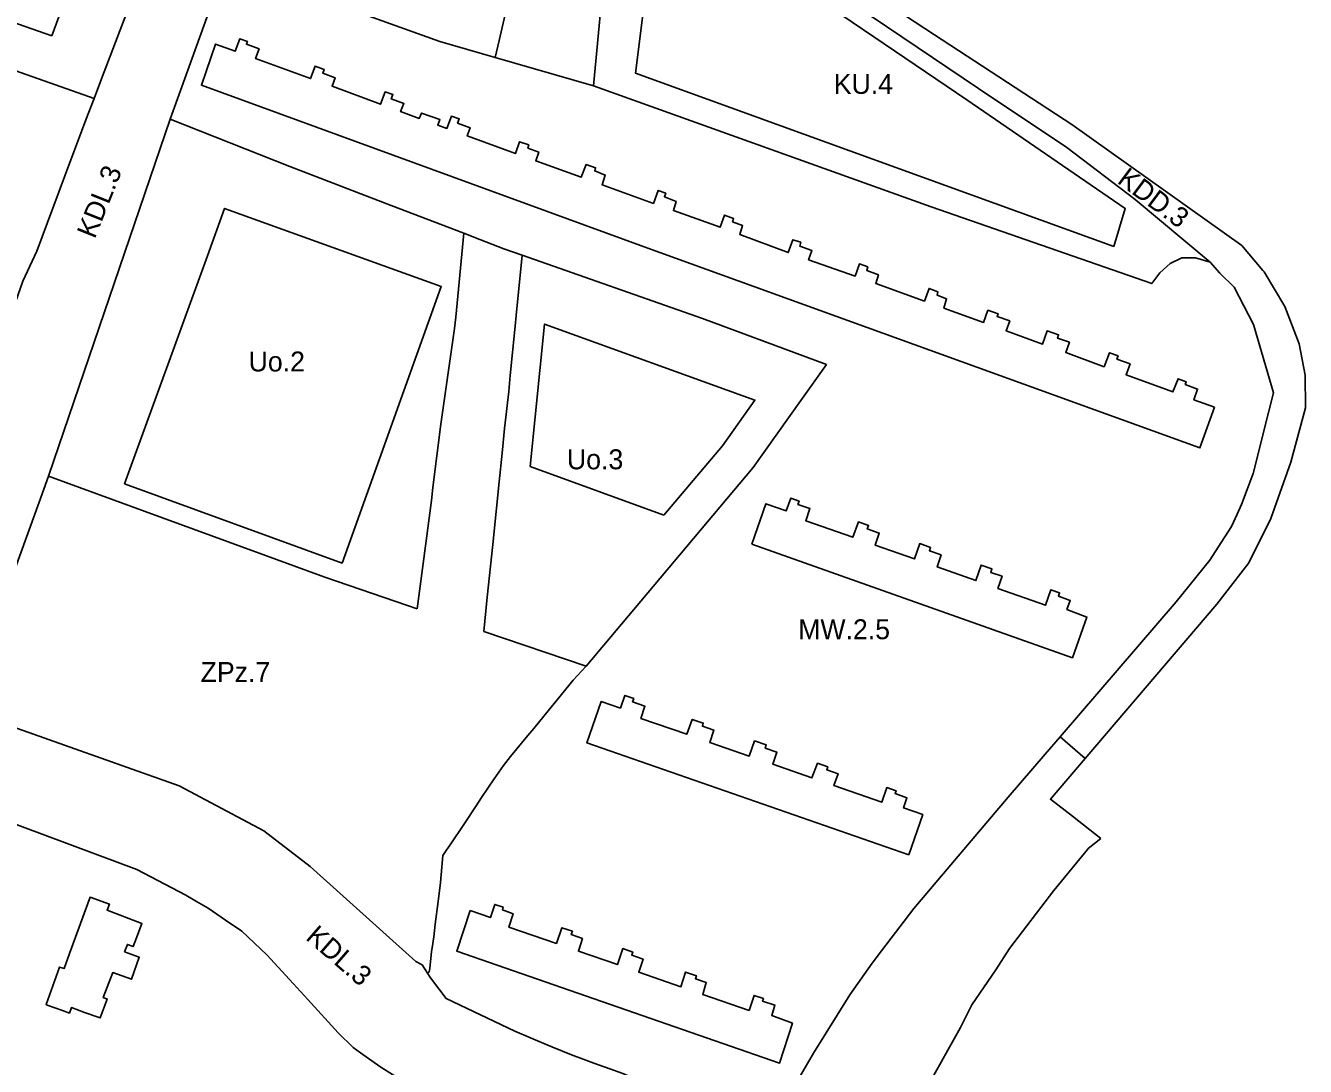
# Model space of a CAD drawing. Extents: x 7428239 to 7429836, y 5549133 to 5550853.
# Drawn here: x 7429316.4 to 7429637.4, y 5550005.5 to 5550266.4 of the extents above; entities that cross this region are included whole.
import ezdxf

# ---------------------------------------------------------------- set-up
doc = ezdxf.new("R2010")
doc.units = 0
for name, color, linetype in [('LIN_linie rozgraniczające', 7, 'Continuous'), ('LIN_nieprzekraczalna linia zabudowy', 7, 'Continuous'), ('LIN_obowiązująca linia zabudowy', 7, 'Continuous'), ('TXT_Oznaczenia Przeznaczenia', 7, 'Continuous')]:
    doc.layers.add(name, color=color, linetype=linetype)

msp = doc.modelspace()

# ---------------------------------------------------------------- linework, layer by layer
at = {"layer": 'LIN_linie rozgraniczające'}
for p, q in [((7429436.32, 5550210.49), (7429440.9, 5550208.88)), ((7429626.71, 5550205.06), (7429621.44, 5550211.32)), ((7429440.9, 5550208.88), (7429486.15, 5550192.99)), ((7429439.22, 5550191.08), (7429437.95, 5550178.73)), ((7429486.15, 5550192.99), (7429517.29, 5550181.44)), ((7429420.58, 5550166.49), (7429424, 5550190.47)), ((7429517.29, 5550181.44), (7429510.86, 5550172.43)), ((7429437.95, 5550178.73), (7429437.57, 5550174.72)), ((7429437.57, 5550174.72), (7429436.55, 5550165.42)), ((7429510.86, 5550172.43), (7429498.86, 5550155.59)), ((7429418.58, 5550150.58), (7429420.58, 5550166.49)), ((7429436.55, 5550165.42), (7429435.95, 5550159.23)), ((7429435.95, 5550159.23), (7429435.2, 5550152.04)), ((7429498.86, 5550155.59), (7429468.91, 5550120.01)), ((7429322.17, 5550153.49), (7429319.78, 5550146.91)), ((7429391.47, 5550128.12), (7429322.17, 5550153.49)), ((7429435.2, 5550152.04), (7429434.43, 5550144.6)), ((7429418.19, 5550147.38), (7429418.58, 5550150.58)), ((7429622.76, 5550150.12), (7429621.32, 5550146.35)), ((7429319.78, 5550146.91), (7429300.94, 5550094.93)), ((7429414.59, 5550120.17), (7429418.19, 5550147.38)), ((7429621.32, 5550146.35), (7429620.24, 5550143.9)), ((7429434.43, 5550144.6), (7429433.58, 5550136.29)), ((7429620.24, 5550143.9), (7429618.82, 5550140.85)), ((7429618.82, 5550140.85), (7429615.52, 5550135.69)), ((7429433.58, 5550136.29), (7429432.18, 5550123.15)), ((7429615.52, 5550135.69), (7429613.41, 5550132.37)), ((7429613.41, 5550132.37), (7429604.96, 5550121.96)), ((7429412.17, 5550121), (7429391.47, 5550128.12)), ((7429432.18, 5550123.15), (7429431.33, 5550114.49)), ((7429414.59, 5550120.17), (7429412.17, 5550121)), ((7429468.91, 5550120.01), (7429456.98, 5550105.85)), ((7429456.98, 5550105.85), (7429431.33, 5550114.49)), ((7429300.94, 5550094.93), (7429354.94, 5550075.82)), ((7429562.83, 5550073.01), (7429572.11, 5550083.77)), ((7429354.94, 5550075.82), (7429376.19, 5550064.53)), ((7429539.14, 5550045.03), (7429562.83, 5550073.01)), ((7429376.19, 5550064.53), (7429387.81, 5550055.56)), ((7429574.24, 5550049.55), (7429582.68, 5550059.88)), ((7429356.56, 5550048.42), (7429344.3, 5550054.83)), ((7429387.81, 5550055.56), (7429414.27, 5550031.8)), ((7429563.14, 5550035.03), (7429574.24, 5550049.55)), ((7429359.3, 5550046.83), (7429356.56, 5550048.42)), ((7429362.17, 5550045.15), (7429359.3, 5550046.83)), ((7429366.58, 5550042.12), (7429362.17, 5550045.15)), ((7429531.03, 5550034.42), (7429539.14, 5550045.03)), ((7429370.62, 5550039.34), (7429366.58, 5550042.12)), ((7429528.7, 5550031.36), (7429531.03, 5550034.42)), ((7429559.75, 5550029.69), (7429563.14, 5550035.03)), ((7429414.27, 5550031.8), (7429415.83, 5550030.94)), ((7429541.25, 5549998.1), (7429550.86, 5550015.24))]:
    msp.add_line(p, q, dxfattribs=at)
for points in [[(7429333.65, 5550248.11), (7429335.43, 5550253.06), (7429343.97, 5550275.43), (7429346.12, 5550281.11), (7429349.62, 5550291.37), (7429352.13, 5550298.07), (7429354.31, 5550304.49), (7429358.66, 5550316.28), (7429359.7, 5550319.12), (7429359.85, 5550319.51), (7429360.39, 5550320.84), (7429364.51, 5550332.56), (7429367.83, 5550342), (7429373.86, 5550361.39), (7429373.64, 5550361.47), (7429373.69, 5550361.59), (7429379.7, 5550383.03), (7429382.96, 5550395.63), (7429386.85, 5550410.17), (7429388.64, 5550416.92), (7429387.69, 5550418.78), (7429393.23, 5550417.3), (7429395.22, 5550416.69), (7429395.87, 5550416.55)], [(7429389.87, 5550345.68), (7429388.42, 5550341.87), (7429385.98, 5550335.46), (7429366.61, 5550281.72), (7429352.66, 5550243), (7429322.17, 5550153.49)], [(7429450.22, 5550317.09), (7429458.17, 5550313.11), (7429461.8, 5550311.2), (7429462.58, 5550309.18), (7429463.3, 5550306.22), (7429463.68, 5550302.76), (7429458.81, 5550251.34), (7429434.17, 5550258.44), (7429420.31, 5550262.43), (7429366.61, 5550281.72)], [(7429450.22, 5550317.09), (7429447.11, 5550312.82), (7429446.17, 5550308.93), (7429444.68, 5550302.56), (7429442.66, 5550294.78), (7429442.04, 5550291.98), (7429440.91, 5550287.07), (7429439.37, 5550280.38), (7429437.82, 5550273.93), (7429437.46, 5550272.49), (7429435.18, 5550262.68), (7429434.17, 5550258.44)], [(7429621.44, 5550211.32), (7429578.76, 5550241.61), (7429544.37, 5550264.14), (7429461.51, 5550318.42)], [(7429478.7, 5550302.35), (7429555.39, 5550250.67)], [(7429333.65, 5550248.11), (7429309.59, 5550256.62), (7429296, 5550261.33), (7429292.19, 5550263.04), (7429286.94, 5550264.84), (7429266.96, 5550271.69), (7429262.68, 5550273.49), (7429251.91, 5550277.34)], [(7429458.81, 5550251.34), (7429543.48, 5550220.97), (7429598.84, 5550201.74), (7429600.83, 5550204.41), (7429603.44, 5550206.78), (7429606.33, 5550208.18), (7429609.79, 5550208.21), (7429613.46, 5550207.08)], [(7429555.39, 5550250.67), (7429577.57, 5550235.89), (7429594.67, 5550222.82), (7429613.46, 5550207.08)], [(7429333.65, 5550248.11), (7429331.56, 5550242.76), (7429326.13, 5550228.5), (7429319.2, 5550209.88), (7429315.74, 5550202.36), (7429312.59, 5550193.52), (7429311.01, 5550189.1), (7429308.85, 5550183.07), (7429307.07, 5550178.6), (7429304.85, 5550172.59), (7429303.13, 5550168.26), (7429301.36, 5550163.38), (7429299.9, 5550158.83), (7429293.53, 5550140.62), (7429292.82, 5550138.68), (7429286.13, 5550119.8), (7429279.68, 5550102.63)], [(7429352.66, 5550243), (7429382.65, 5550231.12), (7429408.1, 5550221.34), (7429426.28, 5550214.35), (7429430.36, 5550212.78), (7429436.32, 5550210.49)], [(7429426.28, 5550214.35), (7429424.3, 5550193.34), (7429424, 5550190.47)], [(7429440.9, 5550208.88), (7429439.43, 5550193.75), (7429439.22, 5550191.08)], [(7429624.31, 5550191.5), (7429619.48, 5550200.83), (7429615.91, 5550204.36), (7429613.46, 5550207.08)], [(7429632.23, 5550195.98), (7429627.06, 5550204.65), (7429626.71, 5550205.06)], [(7429615.16, 5550121.37), (7429623.18, 5550131.69), (7429628.73, 5550142.8), (7429633.73, 5550156.94), (7429637.36, 5550170.6), (7429637.27, 5550178.76), (7429635.82, 5550186.66), (7429632.23, 5550195.98)], [(7429624.31, 5550191.5), (7429629.34, 5550174.38), (7429628.19, 5550169.76)], [(7429628.19, 5550169.76), (7429624.28, 5550154.09), (7429622.76, 5550150.12)], [(7429604.96, 5550121.96), (7429575.82, 5550088.08), (7429572.11, 5550083.77)], [(7429586.07, 5550062.64), (7429578.92, 5550068.18), (7429573.41, 5550072.44), (7429582.13, 5550082.66), (7429615.16, 5550121.37)], [(7429456.98, 5550105.85), (7429453.71, 5550102.29), (7429449.73, 5550097.41), (7429447.45, 5550094.59), (7429443.86, 5550090.22), (7429442.37, 5550088.44), (7429438.03, 5550083.14), (7429436.3, 5550080.92), (7429433.9, 5550077.59), (7429430.71, 5550072.89), (7429429.42, 5550070.78), (7429426.31, 5550066.15), (7429423.03, 5550061.29), (7429421.9, 5550059.62), (7429421.03, 5550058.33), (7429420.42, 5550051.59), (7429419.85, 5550046.84), (7429419.15, 5550041.1), (7429418.77, 5550037.98), (7429418.34, 5550035.23), (7429418.19, 5550034.29), (7429417.81, 5550029.99), (7429417.58, 5550029.21), (7429417.19, 5550028.83)], [(7429582.13, 5550082.66), (7429575.82, 5550088.08)], [(7429286.07, 5550078.43), (7429310.06, 5550067.61), (7429344.3, 5550054.83)], [(7429582.68, 5550059.88), (7429582.91, 5550060.07), (7429586.07, 5550062.64)], [(7429394.76, 5550013.85), (7429387.17, 5550022.23), (7429382.56, 5550027.27), (7429376.9, 5550033.44), (7429370.62, 5550039.34)], [(7429415.83, 5550030.94), (7429417.19, 5550028.83), (7429417.93, 5550027.68)], [(7429503.29, 5549989.64), (7429507.45, 5549997.62), (7429514.02, 5550008.76), (7429523.15, 5550023.38), (7429528.7, 5550031.36)], [(7429417.93, 5550027.68), (7429421.87, 5550022.5), (7429439.14, 5550014.31), (7429443.05, 5550012.66), (7429446.38, 5550011.19), (7429448.41, 5550010.38), (7429453.35, 5550008.35), (7429456.2, 5550007.29), (7429458.89, 5550006.3), (7429462.96, 5550004.84), (7429466.18, 5550003.65), (7429468.38, 5550002.81), (7429473.58, 5550000.83), (7429480.45, 5549998.32), (7429484.71, 5549996.72), (7429489.55, 5549994.94), (7429491.29, 5549994.27), (7429494.59, 5549992.97), (7429498.65, 5549991.43), (7429502.37, 5549990.02), (7429503.29, 5549989.64)], [(7429550.86, 5550015.24), (7429553.73, 5550020.94), (7429559.75, 5550029.69)], [(7429426.24, 5549993.73), (7429424.64, 5549994.76), (7429412.09, 5550001.09), (7429405.27, 5550005.47), (7429400.38, 5550008.88), (7429398.57, 5550010.23), (7429394.76, 5550013.85)]]:
    msp.add_lwpolyline(points, dxfattribs=at)
at = {"layer": 'LIN_nieprzekraczalna linia zabudowy'}
msp.add_line((7429442.93, 5550155.91), (7429476.48, 5550143.68), dxfattribs=at)
for points in [[(7429322.96, 5550263.85), (7429328.47, 5550278.88), (7429273.69, 5550298.26), (7429272.97, 5550296.18), (7429261.14, 5550300.29), (7429258.2, 5550291.73), (7429266.2, 5550288.95), (7429264.85, 5550284.79), (7429268.2, 5550283.68), (7429272.92, 5550282.14), (7429271.38, 5550277.36), (7429278.96, 5550274.79), (7429277.67, 5550270.62), (7429288.11, 5550267.04), (7429290.88, 5550275.1), (7429322.96, 5550263.85)], [(7429589.36, 5550211.02), (7429592.18, 5550220.57), (7429552.48, 5550247.81), (7429500.37, 5550283.17), (7429475.05, 5550299.98), (7429469.39, 5550254.48), (7429589.36, 5550211.02)], [(7429395.81, 5550131.63), (7429420.65, 5550200.97), (7429366.33, 5550220.6), (7429362, 5550208.69), (7429341.22, 5550151.54), (7429395.81, 5550131.63)], [(7429476.48, 5550143.68), (7429491.16, 5550161.07), (7429499.33, 5550172.54), (7429446.57, 5550191.6), (7429442.93, 5550155.91)]]:
    msp.add_lwpolyline(points, dxfattribs=at)
at = {"layer": 'LIN_obowiązująca linia zabudowy'}
for points in [[(7429614.58, 5550170.73), (7429609.42, 5550172.63), (7429610.31, 5550175.29), (7429607.24, 5550176.45), (7429607.47, 5550177.13), (7429605.42, 5550177.87), (7429604.13, 5550174.57), (7429592.4, 5550178.87), (7429593.4, 5550181.59), (7429590.09, 5550182.79), (7429590.4, 5550183.62), (7429588.2, 5550184.4), (7429586.88, 5550180.9), (7429577.28, 5550184.42), (7429578.2, 5550187.04), (7429575.19, 5550188.09), (7429575.46, 5550188.85), (7429572.6, 5550189.86), (7429571.43, 5550186.57), (7429562.3, 5550189.92), (7429563.22, 5550192.36), (7429560.03, 5550193.48), (7429560.28, 5550194.16), (7429557.76, 5550195.04), (7429556.63, 5550192), (7429546.69, 5550195.6), (7429547.37, 5550197.93), (7429544.98, 5550198.85), (7429545.18, 5550199.69), (7429543, 5550200.53), (7429541.82, 5550197.37), (7429529.6, 5550201.75), (7429530.27, 5550203.97), (7429527.35, 5550205.04), (7429527.6, 5550205.93), (7429525.51, 5550206.66), (7429524.42, 5550203.6), (7429512.77, 5550207.7), (7429513.59, 5550210.07), (7429510.54, 5550211.16), (7429510.79, 5550212.09), (7429508.83, 5550212.73), (7429507.68, 5550209.51), (7429495.52, 5550214.05), (7429496.23, 5550216.27), (7429493.73, 5550217.2), (7429493.96, 5550218.02), (7429491.68, 5550218.9), (7429490.58, 5550215.88), (7429478.89, 5550220.03), (7429479.55, 5550222.32), (7429476.63, 5550223.49), (7429476.93, 5550224.37), (7429475.06, 5550225.09), (7429473.87, 5550221.82), (7429461, 5550226.51), (7429461.77, 5550228.95), (7429459.13, 5550229.97), (7429459.34, 5550230.77), (7429456.98, 5550231.57), (7429455.77, 5550228.41), (7429444.35, 5550232.5), (7429445.09, 5550234.72), (7429442.38, 5550235.71), (7429442.61, 5550236.53), (7429440.29, 5550237.31), (7429439.25, 5550234.32), (7429427.15, 5550238.78), (7429427.92, 5550240.8), (7429424.74, 5550241.97), (7429425.15, 5550243.04), (7429423.22, 5550243.71), (7429422.05, 5550240.64), (7429419.79, 5550241.44), (7429420.33, 5550242.86), (7429415.73, 5550244.5), (7429415.12, 5550243.16), (7429410.44, 5550244.87), (7429411.29, 5550246.88), (7429408.11, 5550248.05), (7429408.52, 5550249.12), (7429406.58, 5550249.79), (7429405.41, 5550246.71), (7429393.27, 5550251.2), (7429394.04, 5550253.33), (7429390.93, 5550254.46), (7429391.28, 5550255.43), (7429389.02, 5550256.25), (7429387.89, 5550253.15), (7429374.1, 5550258.15), (7429374.98, 5550260.59), (7429371.78, 5550261.75), (7429372.03, 5550262.42), (7429370.15, 5550263.11), (7429369.01, 5550259.99), (7429364.02, 5550261.8), (7429360.5, 5550251.47), (7429471.51, 5550210.99), (7429610.91, 5550160.53)], [(7429498.51, 5550136.4), (7429578.94, 5550107.93), (7429582.56, 5550118.12), (7429577.55, 5550120.04), (7429578.38, 5550122.32), (7429575.48, 5550123.34), (7429575.73, 5550124.21), (7429573.52, 5550124.99), (7429572.22, 5550121.11), (7429560.26, 5550125.32), (7429561.3, 5550128.34), (7429558.45, 5550129.34), (7429558.73, 5550130.2), (7429556.03, 5550131.15), (7429554.72, 5550127.26), (7429545.02, 5550130.68), (7429545.99, 5550133.73), (7429543.08, 5550134.76), (7429543.36, 5550135.61), (7429540.63, 5550136.57), (7429539.29, 5550132.69), (7429529.49, 5550136.14), (7429530.48, 5550139.2), (7429527.5, 5550140.24), (7429527.81, 5550141.08), (7429525.27, 5550141.98), (7429523.86, 5550138.12), (7429512.05, 5550142.27), (7429513.09, 5550145.32), (7429510.11, 5550146.37), (7429510.39, 5550147.22), (7429508.3, 5550147.95), (7429507.11, 5550144.76), (7429502.04, 5550146.52)], [(7429537.92, 5550058.5), (7429541.4, 5550068.61), (7429536.6, 5550070.28), (7429537.41, 5550072.77), (7429534.46, 5550073.85), (7429534.71, 5550074.59), (7429532.36, 5550075.38), (7429531.12, 5550071.71), (7429519.14, 5550075.88), (7429520.18, 5550078.83), (7429517.32, 5550079.83), (7429517.59, 5550080.57), (7429515.01, 5550081.49), (7429513.62, 5550077.8), (7429503.77, 5550081.23), (7429504.83, 5550084.23), (7429501.89, 5550085.26), (7429502.17, 5550086.09), (7429499.21, 5550087.08), (7429497.88, 5550083.27), (7429487.97, 5550086.72), (7429488.98, 5550089.78), (7429486.16, 5550090.75), (7429486.37, 5550091.54), (7429483.59, 5550092.47), (7429482.2, 5550088.73), (7429470.73, 5550092.72), (7429471.73, 5550095.78), (7429468.63, 5550096.89), (7429468.93, 5550097.69), (7429466.72, 5550098.49), (7429465.6, 5550095.3), (7429460.75, 5550096.94), (7429457.2, 5550086.59)], [(7429341.22, 5550034.18), (7429341.93, 5550036.05), (7429343.38, 5550035.5), (7429344.22, 5550037.71), (7429345.6, 5550041.33), (7429336.85, 5550044.65), (7429337.42, 5550046.16), (7429332.58, 5550047.86), (7429327.46, 5550033.81), (7429326.06, 5550029.98), (7429324.92, 5550030.38), (7429321.54, 5550020.95), (7429321.86, 5550020.84), (7429325.68, 5550019.47), (7429327.42, 5550018.85), (7429327.9, 5550020.2), (7429331.21, 5550019.01), (7429334.88, 5550017.7), (7429335.09, 5550017.62), (7429336.88, 5550022.35), (7429335.88, 5550022.73), (7429338.27, 5550029.01), (7429342.96, 5550027.34), (7429344.92, 5550032.83)], [(7429427.87, 5550044.59), (7429424.53, 5550034.33), (7429505.51, 5550006.31), (7429508.71, 5550016.35), (7429503.53, 5550018.2), (7429504.34, 5550020.83), (7429501.23, 5550021.84), (7429501.43, 5550022.47), (7429499.1, 5550023.26), (7429497.83, 5550019.5), (7429486.23, 5550023.51), (7429487.09, 5550026.47), (7429484.4, 5550027.46), (7429484.64, 5550028.19), (7429481.92, 5550029.1), (7429480.74, 5550025.42), (7429470.17, 5550029.08), (7429471.26, 5550032.32), (7429468.43, 5550033.35), (7429468.68, 5550034.13), (7429466.18, 5550034.99), (7429464.82, 5550030.98), (7429455.03, 5550034.34), (7429456.06, 5550037.53), (7429453.24, 5550038.52), (7429453.53, 5550039.35), (7429450.89, 5550040.24), (7429449.54, 5550036.29), (7429437.6, 5550040.37), (7429438.65, 5550043.75), (7429435.98, 5550044.72), (7429436.18, 5550045.39), (7429434.06, 5550046.1), (7429433, 5550042.8)]]:
    msp.add_lwpolyline(points, close=True, dxfattribs=at)

# ---------------------------------------------------------------- texts
at = {"layer": 'TXT_Oznaczenia Przeznaczenia'}
for s, p in [('KU.4', (7429519.08, 5550249.3)), ('Uo.2', (7429372.34, 5550179.7)), ('Uo.3', (7429452.17, 5550155.18)), ('MW.2.5', (7429510.16, 5550112.57)), ('ZPz.7', (7429360.31, 5550101.86))]:
    msp.add_text(s, height=5, dxfattribs=at).set_placement(p)
for s, rotation, p in [('KDL.3', 68.1573, (7429333.76, 5550212.77)), ('KDD.3', 323.3413, (7429589.92, 5550227.15)), ('KDL.3', 319.0392, (7429386.41, 5550037.47))]:
    msp.add_text(s, height=5, rotation=rotation, dxfattribs=at).set_placement(p)

doc.saveas('drawing.dxf')
